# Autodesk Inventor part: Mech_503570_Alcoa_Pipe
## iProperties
Shininess: 64.0
Length Units: 11272
Angle Units: 11279
Time Units: 11290
Mass Units: 11286
Length Display Precision: 3
Angle Display Precision: 2
Compacted: True
Part Number: Mech_503570_Alcoa_Pipe
Document SubType Name: Modeling
Created: 2005-05
Designer: John Blackburn
Manufacturer: Standard
Standards Organization: Custom
Material: Aluminum-6061
Density: 0.0
Volumn: 0.0
Area: 0.0
PropertySet Name: Model Information
Control State: 0
Master: False
Checked Out: False
Author: John Blackburn
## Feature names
1. Extrusion1
